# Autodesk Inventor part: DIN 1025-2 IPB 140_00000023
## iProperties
Created: 2006-02
Part Number: DIN 1025-2 IPB 140_00000023
Material: Default
Document SubType Name: Modeling
Designer: 40664
Manufacturer: Standard
Standards Organization: Custom
Stock Number: DIN 1025-2 IPB 140
Mass: 10266.5 g
Surface Area: 19334.9 cm^2
Volume: 10266.5 cm^3
Density: 1 g/cm^3
G_L: 2390.000 mm
G_W: 140.000 mm
G_H: 140.000 mm
AFG_Item: IPB 140
CSToolsMass: 10.0
CSToolsVolume: 10266466.0
CSToolsArea: 19335.0
Author: 40664
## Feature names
1. AFG_Detailed_DIN 1025-2 IPB 140_00000023 [Extrusion]
2. AFG_Simplified_DIN 1025-2 IPB 140_00000023 [Extrusion]
